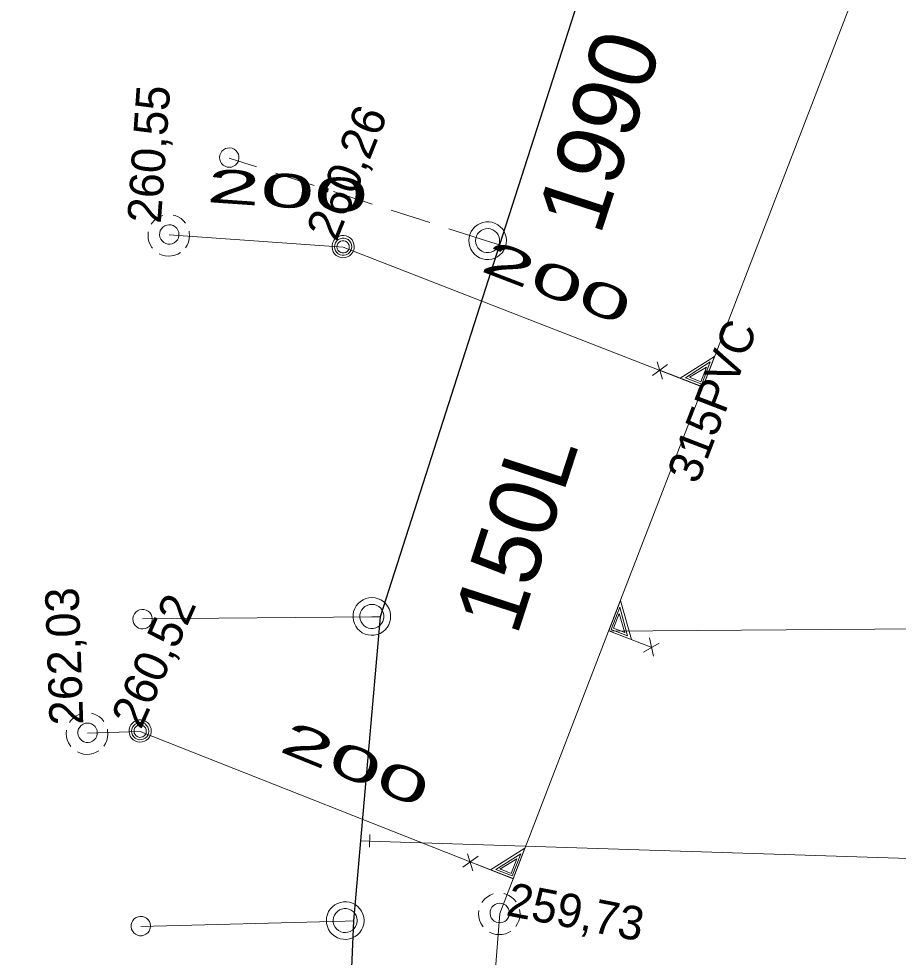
# Model space of a CAD drawing. Extents: x -732096 to -731933, y -1048703 to -1047964.
# Drawn here: x -732046.89 to -732026, y -1048029.6 to -1048007.32 of the extents above; entities that cross this region are included whole.
import ezdxf

# ---------------------------------------------------------------- set-up
doc = ezdxf.new("R2010")
doc.units = 0
doc.header["$LTSCALE"] = 0.32
doc.linetypes.add('MEDIUM_DASHED', pattern=[4.5, 3, -1.5])
doc.layers.add('1', color=7, linetype='Continuous')
for name, color, linetype, lineweight in [('18', 7, 'Continuous', 13), ('20', 7, 'Continuous', 13), ('49', 7, 'Continuous', 13), ('8', 7, 'Continuous', 13)]:
    doc.layers.add(name, color=color, linetype=linetype, lineweight=lineweight)

msp = doc.modelspace()

# ---------------------------------------------------------------- linework, layer by layer
at = {"layer": '18'}
for p, q in [((-732031.842, -1048015.786), (-732031.481, -1048015.527)), ((-732031.733, -1048015.465), (-732031.602, -1048015.874)), ((-732031.814, -1048022.451), (-732031.909, -1048022.017)), ((-732031.682, -1048022.14), (-732032.053, -1048022.355)), ((-732036.237, -1048027.14), (-732036.106, -1048027.549)), ((-732036.346, -1048027.461), (-732035.985, -1048027.202))]:
    msp.add_line(p, q, dxfattribs=at)
for points in [[(-732043.473, -1048011.987), (-732043.544, -1048012.015), (-732043.61, -1048012.054), (-732043.671, -1048012.102), (-732043.722, -1048012.159), (-732043.745, -1048012.193)], [(-732042.931, -1048012.17), (-732042.982, -1048012.112), (-732043.039, -1048012.062), (-732043.105, -1048012.021), (-732043.176, -1048011.992), (-732043.225, -1048011.978)], [(-732043.818, -1048012.379), (-732043.823, -1048012.456), (-732043.818, -1048012.533), (-732043.801, -1048012.608), (-732043.772, -1048012.679), (-732043.732, -1048012.745), (-732043.717, -1048012.767)], [(-732042.936, -1048012.756), (-732042.896, -1048012.691), (-732042.865, -1048012.621), (-732042.845, -1048012.546), (-732042.838, -1048012.47), (-732042.843, -1048012.393), (-732042.848, -1048012.358)], [(-732043.559, -1048012.896), (-732043.49, -1048012.927), (-732043.414, -1048012.946), (-732043.338, -1048012.953), (-732043.262, -1048012.948), (-732043.186, -1048012.931), (-732043.115, -1048012.903), (-732043.054, -1048012.868)], [(-732031.67, -1048015.661), (-732030.648, -1048016.056), (-732030.37, -1048015.337), (-732031.187, -1048015.848)], [(-732031.058, -1048015.843), (-732030.67, -1048015.993), (-732030.467, -1048015.465), (-732031.059, -1048015.842)], [(-732030.963, -1048015.829), (-732030.692, -1048015.934), (-732030.558, -1048015.588), (-732030.964, -1048015.831)], [(-732031.86, -1048022.242), (-732032.881, -1048021.848), (-732032.604, -1048021.13), (-732032.342, -1048022.056)], [(-732032.435, -1048021.967), (-732032.822, -1048021.817), (-732032.618, -1048021.289), (-732032.433, -1048021.968)], [(-732032.495, -1048021.893), (-732032.768, -1048021.788), (-732032.634, -1048021.441), (-732032.496, -1048021.894)], [(-732044.872, -1048024), (-732044.922, -1048023.942), (-732044.98, -1048023.892), (-732045.045, -1048023.851), (-732045.116, -1048023.822), (-732045.165, -1048023.808)], [(-732045.413, -1048023.817), (-732045.484, -1048023.845), (-732045.551, -1048023.884), (-732045.611, -1048023.932), (-732045.662, -1048023.989), (-732045.686, -1048024.023)], [(-732045.758, -1048024.209), (-732045.764, -1048024.286), (-732045.759, -1048024.363), (-732045.742, -1048024.438), (-732045.713, -1048024.509), (-732045.673, -1048024.575), (-732045.657, -1048024.597)], [(-732044.877, -1048024.586), (-732044.836, -1048024.521), (-732044.805, -1048024.451), (-732044.786, -1048024.376), (-732044.778, -1048024.3), (-732044.783, -1048024.223), (-732044.789, -1048024.188)], [(-732045.5, -1048024.726), (-732045.43, -1048024.757), (-732045.355, -1048024.776), (-732045.279, -1048024.783), (-732045.202, -1048024.778), (-732045.127, -1048024.761), (-732045.055, -1048024.733), (-732044.995, -1048024.698)], [(-732036.174, -1048027.336), (-732035.152, -1048027.731), (-732034.874, -1048027.012), (-732035.691, -1048027.523)], [(-732035.562, -1048027.518), (-732035.174, -1048027.668), (-732034.971, -1048027.14), (-732035.563, -1048027.517)], [(-732035.467, -1048027.504), (-732035.196, -1048027.609), (-732035.062, -1048027.263), (-732035.468, -1048027.506)], [(-732035.622, -1048028.097), (-732035.693, -1048028.125), (-732035.76, -1048028.164), (-732035.82, -1048028.212), (-732035.871, -1048028.269), (-732035.895, -1048028.303)], [(-732035.081, -1048028.28), (-732035.131, -1048028.222), (-732035.189, -1048028.172), (-732035.254, -1048028.131), (-732035.325, -1048028.102), (-732035.374, -1048028.088)], [(-732035.086, -1048028.866), (-732035.045, -1048028.801), (-732035.014, -1048028.731), (-732034.995, -1048028.656), (-732034.987, -1048028.58), (-732034.992, -1048028.503), (-732034.998, -1048028.468)], [(-732035.967, -1048028.489), (-732035.973, -1048028.566), (-732035.968, -1048028.643), (-732035.951, -1048028.718), (-732035.922, -1048028.789), (-732035.882, -1048028.855), (-732035.866, -1048028.877)], [(-732035.709, -1048029.006), (-732035.639, -1048029.037), (-732035.564, -1048029.056), (-732035.488, -1048029.063), (-732035.411, -1048029.058), (-732035.336, -1048029.041), (-732035.264, -1048029.013), (-732035.204, -1048028.978)]]:
    msp.add_lwpolyline(points, dxfattribs=at)
for points in [[(-732043.088, -1048012.439), (-732043.095, -1048012.387), (-732043.112, -1048012.337), (-732043.141, -1048012.293), (-732043.179, -1048012.256), (-732043.223, -1048012.229), (-732043.274, -1048012.213), (-732043.326, -1048012.208), (-732043.377, -1048012.215), (-732043.426, -1048012.234), (-732043.47, -1048012.264), (-732043.505, -1048012.303), (-732043.532, -1048012.348), (-732043.546, -1048012.399), (-732043.549, -1048012.451), (-732043.541, -1048012.503), (-732043.521, -1048012.551), (-732043.49, -1048012.594), (-732043.451, -1048012.629), (-732043.404, -1048012.653), (-732043.353, -1048012.667), (-732043.301, -1048012.669), (-732043.25, -1048012.659), (-732043.201, -1048012.637), (-732043.159, -1048012.605), (-732043.127, -1048012.565), (-732043.103, -1048012.518), (-732043.09, -1048012.467)], [(-732038.926, -1048012.727), (-732038.931, -1048012.671), (-732038.948, -1048012.618), (-732038.977, -1048012.569), (-732039.016, -1048012.528), (-732039.061, -1048012.496), (-732039.114, -1048012.474), (-732039.169, -1048012.463), (-732039.225, -1048012.465), (-732039.279, -1048012.478), (-732039.33, -1048012.503), (-732039.375, -1048012.538), (-732039.411, -1048012.581), (-732039.436, -1048012.631), (-732039.451, -1048012.686), (-732039.453, -1048012.742), (-732039.445, -1048012.797), (-732039.424, -1048012.85), (-732039.392, -1048012.896), (-732039.352, -1048012.935), (-732039.304, -1048012.965), (-732039.252, -1048012.984), (-732039.196, -1048012.991), (-732039.139, -1048012.987), (-732039.085, -1048012.97), (-732039.036, -1048012.943), (-732038.995, -1048012.905), (-732038.962, -1048012.86), (-732038.938, -1048012.809), (-732038.926, -1048012.754)], [(-732038.985, -1048012.73), (-732038.99, -1048012.681), (-732039.009, -1048012.635), (-732039.036, -1048012.594), (-732039.073, -1048012.561), (-732039.117, -1048012.539), (-732039.166, -1048012.527), (-732039.215, -1048012.527), (-732039.262, -1048012.539), (-732039.306, -1048012.562), (-732039.343, -1048012.595), (-732039.372, -1048012.636), (-732039.389, -1048012.683), (-732039.394, -1048012.732), (-732039.387, -1048012.781), (-732039.37, -1048012.827), (-732039.342, -1048012.867), (-732039.304, -1048012.9), (-732039.261, -1048012.922), (-732039.212, -1048012.934), (-732039.163, -1048012.933), (-732039.115, -1048012.921), (-732039.071, -1048012.897), (-732039.034, -1048012.864), (-732039.007, -1048012.823), (-732038.99, -1048012.776)], [(-732039.044, -1048012.734), (-732039.049, -1048012.692), (-732039.066, -1048012.654), (-732039.095, -1048012.623), (-732039.129, -1048012.6), (-732039.169, -1048012.589), (-732039.212, -1048012.589), (-732039.252, -1048012.601), (-732039.286, -1048012.624), (-732039.313, -1048012.656), (-732039.33, -1048012.694), (-732039.335, -1048012.735), (-732039.33, -1048012.777), (-732039.311, -1048012.814), (-732039.284, -1048012.846), (-732039.247, -1048012.868), (-732039.208, -1048012.879), (-732039.166, -1048012.878), (-732039.125, -1048012.865), (-732039.092, -1048012.842), (-732039.065, -1048012.809), (-732039.049, -1048012.771)], [(-732043.746, -1048024.227), (-732043.752, -1048024.171), (-732043.769, -1048024.118), (-732043.798, -1048024.069), (-732043.836, -1048024.028), (-732043.882, -1048023.996), (-732043.934, -1048023.974), (-732043.989, -1048023.963), (-732044.045, -1048023.965), (-732044.1, -1048023.978), (-732044.151, -1048024.003), (-732044.195, -1048024.038), (-732044.231, -1048024.081), (-732044.256, -1048024.131), (-732044.271, -1048024.186), (-732044.274, -1048024.242), (-732044.265, -1048024.297), (-732044.244, -1048024.35), (-732044.213, -1048024.396), (-732044.173, -1048024.435), (-732044.125, -1048024.465), (-732044.072, -1048024.484), (-732044.016, -1048024.491), (-732043.96, -1048024.487), (-732043.906, -1048024.47), (-732043.857, -1048024.443), (-732043.815, -1048024.405), (-732043.782, -1048024.36), (-732043.759, -1048024.309), (-732043.747, -1048024.254)], [(-732043.805, -1048024.23), (-732043.811, -1048024.181), (-732043.829, -1048024.135), (-732043.857, -1048024.094), (-732043.894, -1048024.061), (-732043.938, -1048024.039), (-732043.986, -1048024.027), (-732044.035, -1048024.027), (-732044.083, -1048024.039), (-732044.127, -1048024.062), (-732044.164, -1048024.095), (-732044.192, -1048024.136), (-732044.209, -1048024.183), (-732044.215, -1048024.232), (-732044.208, -1048024.281), (-732044.19, -1048024.327), (-732044.162, -1048024.367), (-732044.125, -1048024.4), (-732044.081, -1048024.422), (-732044.032, -1048024.434), (-732043.983, -1048024.433), (-732043.935, -1048024.421), (-732043.892, -1048024.397), (-732043.855, -1048024.364), (-732043.827, -1048024.323), (-732043.811, -1048024.276)], [(-732045.029, -1048024.269), (-732045.035, -1048024.217), (-732045.053, -1048024.167), (-732045.081, -1048024.123), (-732045.119, -1048024.086), (-732045.164, -1048024.059), (-732045.214, -1048024.043), (-732045.266, -1048024.038), (-732045.318, -1048024.045), (-732045.367, -1048024.064), (-732045.411, -1048024.094), (-732045.446, -1048024.133), (-732045.472, -1048024.178), (-732045.487, -1048024.229), (-732045.49, -1048024.281), (-732045.482, -1048024.333), (-732045.461, -1048024.381), (-732045.431, -1048024.424), (-732045.391, -1048024.459), (-732045.345, -1048024.483), (-732045.294, -1048024.497), (-732045.242, -1048024.499), (-732045.19, -1048024.489), (-732045.142, -1048024.467), (-732045.1, -1048024.435), (-732045.067, -1048024.395), (-732045.043, -1048024.348), (-732045.031, -1048024.297)], [(-732043.864, -1048024.234), (-732043.87, -1048024.192), (-732043.887, -1048024.154), (-732043.915, -1048024.123), (-732043.95, -1048024.1), (-732043.99, -1048024.089), (-732044.032, -1048024.089), (-732044.072, -1048024.101), (-732044.107, -1048024.124), (-732044.134, -1048024.156), (-732044.151, -1048024.194), (-732044.156, -1048024.235), (-732044.15, -1048024.277), (-732044.132, -1048024.314), (-732044.104, -1048024.346), (-732044.068, -1048024.368), (-732044.028, -1048024.379), (-732043.986, -1048024.378), (-732043.946, -1048024.365), (-732043.912, -1048024.342), (-732043.885, -1048024.309), (-732043.869, -1048024.271)], [(-732035.238, -1048028.549), (-732035.244, -1048028.497), (-732035.262, -1048028.447), (-732035.29, -1048028.403), (-732035.328, -1048028.366), (-732035.373, -1048028.339), (-732035.423, -1048028.323), (-732035.475, -1048028.318), (-732035.527, -1048028.325), (-732035.576, -1048028.344), (-732035.62, -1048028.374), (-732035.655, -1048028.413), (-732035.681, -1048028.458), (-732035.696, -1048028.509), (-732035.699, -1048028.561), (-732035.691, -1048028.613), (-732035.67, -1048028.661), (-732035.64, -1048028.704), (-732035.6, -1048028.739), (-732035.554, -1048028.763), (-732035.503, -1048028.777), (-732035.451, -1048028.779), (-732035.399, -1048028.769), (-732035.351, -1048028.747), (-732035.309, -1048028.715), (-732035.276, -1048028.675), (-732035.252, -1048028.628), (-732035.24, -1048028.577)]]:
    msp.add_lwpolyline(points, close=True, dxfattribs=at)
at = {"layer": '20'}
for points in [[(-732035.469, -1048028.56), (-732035.152, -1048027.738), (-732032.882, -1048021.854), (-732030.648, -1048016.063), (-732026.359, -1048004.95)], [(-732035.469, -1048028.56), (-732035.152, -1048027.738), (-732032.882, -1048021.854), (-732030.648, -1048016.063), (-732026.359, -1048004.95)], [(-732072.387, -1048040.394), (-732045.426, -1048038.914), (-732043.129, -1048038.788), (-732036.239, -1048038.41), (-732035.469, -1048028.56)], [(-732072.387, -1048040.394), (-732045.426, -1048038.914), (-732043.129, -1048038.788), (-732036.239, -1048038.41), (-732035.469, -1048028.56)]]:
    msp.add_lwpolyline(points, dxfattribs=at)
at = {"layer": '49'}
for p, q in [((-732043.32, -1048012.45), (-732039.19, -1048012.74)), ((-732043.32, -1048012.45), (-732039.19, -1048012.74)), ((-732039.19, -1048012.74), (-732030.648, -1048016.063)), ((-732039.19, -1048012.74), (-732030.648, -1048016.063)), ((-732015.73, -1048021.73), (-732032.882, -1048021.854)), ((-732015.73, -1048021.73), (-732032.882, -1048021.854))]:
    msp.add_line(p, q, dxfattribs=at)
msp.add_lwpolyline([(-732045.26, -1048024.28), (-732044.01, -1048024.24), (-732035.152, -1048027.738)], dxfattribs=at)
msp.add_lwpolyline([(-732045.26, -1048024.28), (-732044.01, -1048024.24), (-732035.152, -1048027.738)], dxfattribs=at)
at = {"layer": '8', "linetype": 'MEDIUM_DASHED'}
for p, q in [((-732035.761, -1048012.597), (-732041.897, -1048010.626)), ((-732035.475, -1048012.689), (-732035.761, -1048012.597))]:
    msp.add_line(p, q, dxfattribs=at)
at = {"layer": '8'}
for p, q in [((-732038.51, -1048021.52), (-732043.954, -1048021.564)), ((-732038.309, -1048021.518), (-732038.51, -1048021.52)), ((-732038.563, -1048026.985), (-732038.553, -1048026.681)), ((-732038.774, -1048026.833), (-732038.559, -1048026.84)), ((-732038.559, -1048026.84), (-732022.559, -1048027.36)), ((-732039.14, -1048028.74), (-732043.997, -1048028.871)), ((-732038.94, -1048028.735), (-732039.14, -1048028.74))]:
    msp.add_line(p, q, dxfattribs=at)
at = {"layer": '8', "lineweight": 25}
msp.add_lwpolyline([(-732033.399, -1047999.11), (-732033.26, -1048005.79), (-732035.475, -1048012.689), (-732038.309, -1048021.518), (-732038.774, -1048026.833), (-732038.94, -1048028.735), (-732039.3, -1048037.077)], dxfattribs=at)
at = {"layer": '8'}
for points in [[(-732041.673, -1048010.685), (-732041.663, -1048010.634), (-732041.665, -1048010.581), (-732041.678, -1048010.53), (-732041.703, -1048010.483), (-732041.738, -1048010.444), (-732041.78, -1048010.413), (-732041.828, -1048010.393), (-732041.88, -1048010.383), (-732041.932, -1048010.387), (-732041.984, -1048010.402), (-732042.029, -1048010.428), (-732042.067, -1048010.463), (-732042.097, -1048010.507), (-732042.116, -1048010.556), (-732042.124, -1048010.608), (-732042.119, -1048010.66), (-732042.104, -1048010.71), (-732042.076, -1048010.755), (-732042.04, -1048010.792), (-732041.995, -1048010.821), (-732041.946, -1048010.839), (-732041.894, -1048010.845), (-732041.842, -1048010.839), (-732041.792, -1048010.821), (-732041.748, -1048010.793), (-732041.711, -1048010.756), (-732041.684, -1048010.711)], [(-732035.332, -1048012.722), (-732035.315, -1048012.651), (-732035.311, -1048012.578), (-732035.318, -1048012.505), (-732035.337, -1048012.435), (-732035.367, -1048012.368), (-732035.407, -1048012.307), (-732035.457, -1048012.254), (-732035.516, -1048012.209), (-732035.58, -1048012.175), (-732035.65, -1048012.151), (-732035.722, -1048012.14), (-732035.796, -1048012.14), (-732035.867, -1048012.152), (-732035.936, -1048012.176), (-732036.001, -1048012.211), (-732036.059, -1048012.255), (-732036.109, -1048012.31), (-732036.149, -1048012.37), (-732036.179, -1048012.437), (-732036.198, -1048012.508), (-732036.204, -1048012.58), (-732036.199, -1048012.653), (-732036.182, -1048012.725), (-732036.154, -1048012.792), (-732036.115, -1048012.854), (-732036.066, -1048012.908), (-732036.01, -1048012.955), (-732035.946, -1048012.991), (-732035.877, -1048013.017), (-732035.805, -1048013.03), (-732035.732, -1048013.032), (-732035.659, -1048013.022), (-732035.589, -1048013), (-732035.524, -1048012.967), (-732035.465, -1048012.923), (-732035.413, -1048012.872), (-732035.372, -1048012.811), (-732035.34, -1048012.746)], [(-732035.485, -1048012.673), (-732035.473, -1048012.616), (-732035.473, -1048012.557), (-732035.484, -1048012.5), (-732035.508, -1048012.446), (-732035.54, -1048012.398), (-732035.583, -1048012.358), (-732035.633, -1048012.327), (-732035.689, -1048012.307), (-732035.746, -1048012.299), (-732035.805, -1048012.303), (-732035.862, -1048012.319), (-732035.913, -1048012.345), (-732035.959, -1048012.382), (-732035.996, -1048012.428), (-732036.023, -1048012.479), (-732036.04, -1048012.536), (-732036.044, -1048012.594), (-732036.036, -1048012.652), (-732036.016, -1048012.707), (-732035.986, -1048012.758), (-732035.946, -1048012.8), (-732035.898, -1048012.834), (-732035.845, -1048012.858), (-732035.788, -1048012.87), (-732035.729, -1048012.871), (-732035.672, -1048012.859), (-732035.618, -1048012.835), (-732035.571, -1048012.802), (-732035.531, -1048012.759), (-732035.5, -1048012.709)], [(-732038.062, -1048021.543), (-732038.062, -1048021.469), (-732038.075, -1048021.397), (-732038.099, -1048021.328), (-732038.134, -1048021.264), (-732038.178, -1048021.206), (-732038.232, -1048021.156), (-732038.293, -1048021.117), (-732038.36, -1048021.086), (-732038.43, -1048021.068), (-732038.504, -1048021.061), (-732038.577, -1048021.066), (-732038.648, -1048021.084), (-732038.715, -1048021.112), (-732038.777, -1048021.151), (-732038.832, -1048021.2), (-732038.877, -1048021.257), (-732038.913, -1048021.321), (-732038.939, -1048021.389), (-732038.952, -1048021.461), (-732038.954, -1048021.535), (-732038.944, -1048021.607), (-732038.922, -1048021.676), (-732038.889, -1048021.742), (-732038.845, -1048021.801), (-732038.793, -1048021.852), (-732038.733, -1048021.894), (-732038.668, -1048021.926), (-732038.597, -1048021.946), (-732038.524, -1048021.955), (-732038.451, -1048021.952), (-732038.379, -1048021.936), (-732038.311, -1048021.909), (-732038.248, -1048021.872), (-732038.192, -1048021.825), (-732038.145, -1048021.769), (-732038.107, -1048021.707), (-732038.081, -1048021.639), (-732038.065, -1048021.568)], [(-732044.183, -1048021.575), (-732044.177, -1048021.627), (-732044.158, -1048021.677), (-732044.13, -1048021.721), (-732044.092, -1048021.757), (-732044.047, -1048021.784), (-732043.996, -1048021.799), (-732043.944, -1048021.804), (-732043.892, -1048021.796), (-732043.844, -1048021.777), (-732043.8, -1048021.747), (-732043.765, -1048021.707), (-732043.74, -1048021.662), (-732043.725, -1048021.611), (-732043.723, -1048021.559), (-732043.731, -1048021.507), (-732043.752, -1048021.459), (-732043.783, -1048021.416), (-732043.823, -1048021.382), (-732043.869, -1048021.358), (-732043.92, -1048021.345), (-732043.972, -1048021.343), (-732044.024, -1048021.354), (-732044.072, -1048021.376), (-732044.114, -1048021.408), (-732044.147, -1048021.449), (-732044.17, -1048021.496), (-732044.182, -1048021.547)], [(-732038.223, -1048021.53), (-732038.224, -1048021.472), (-732038.238, -1048021.415), (-732038.262, -1048021.362), (-732038.297, -1048021.315), (-732038.34, -1048021.275), (-732038.391, -1048021.246), (-732038.447, -1048021.228), (-732038.505, -1048021.221), (-732038.563, -1048021.227), (-732038.62, -1048021.245), (-732038.671, -1048021.273), (-732038.715, -1048021.31), (-732038.751, -1048021.357), (-732038.777, -1048021.41), (-732038.791, -1048021.466), (-732038.794, -1048021.525), (-732038.784, -1048021.583), (-732038.763, -1048021.638), (-732038.731, -1048021.686), (-732038.69, -1048021.729), (-732038.642, -1048021.76), (-732038.587, -1048021.783), (-732038.53, -1048021.793), (-732038.472, -1048021.792), (-732038.414, -1048021.779), (-732038.361, -1048021.754), (-732038.314, -1048021.719), (-732038.276, -1048021.675), (-732038.247, -1048021.625), (-732038.229, -1048021.569)], [(-732038.693, -1048028.717), (-732038.701, -1048028.644), (-732038.72, -1048028.573), (-732038.751, -1048028.507), (-732038.793, -1048028.447), (-732038.843, -1048028.393), (-732038.901, -1048028.35), (-732038.966, -1048028.317), (-732039.036, -1048028.293), (-732039.108, -1048028.282), (-732039.182, -1048028.283), (-732039.254, -1048028.296), (-732039.323, -1048028.32), (-732039.386, -1048028.355), (-732039.444, -1048028.401), (-732039.494, -1048028.455), (-732039.533, -1048028.516), (-732039.563, -1048028.584), (-732039.581, -1048028.654), (-732039.587, -1048028.727), (-732039.581, -1048028.8), (-732039.563, -1048028.871), (-732039.535, -1048028.938), (-732039.495, -1048029), (-732039.446, -1048029.054), (-732039.389, -1048029.099), (-732039.325, -1048029.135), (-732039.256, -1048029.16), (-732039.184, -1048029.173), (-732039.111, -1048029.174), (-732039.038, -1048029.164), (-732038.968, -1048029.141), (-732038.903, -1048029.107), (-732038.844, -1048029.064), (-732038.794, -1048029.011), (-732038.752, -1048028.95), (-732038.721, -1048028.885), (-732038.701, -1048028.814), (-732038.693, -1048028.742)], [(-732038.854, -1048028.721), (-732038.861, -1048028.663), (-732038.881, -1048028.607), (-732038.91, -1048028.557), (-732038.95, -1048028.514), (-732038.997, -1048028.479), (-732039.051, -1048028.456), (-732039.108, -1048028.443), (-732039.167, -1048028.443), (-732039.224, -1048028.454), (-732039.278, -1048028.477), (-732039.326, -1048028.511), (-732039.366, -1048028.553), (-732039.397, -1048028.602), (-732039.418, -1048028.658), (-732039.426, -1048028.715), (-732039.423, -1048028.774), (-732039.407, -1048028.831), (-732039.381, -1048028.883), (-732039.344, -1048028.928), (-732039.299, -1048028.966), (-732039.247, -1048028.993), (-732039.191, -1048029.009), (-732039.133, -1048029.014), (-732039.075, -1048029.006), (-732039.019, -1048028.988), (-732038.969, -1048028.958), (-732038.926, -1048028.918), (-732038.892, -1048028.871), (-732038.868, -1048028.817), (-732038.856, -1048028.76)], [(-732043.765, -1048028.853), (-732043.772, -1048028.801), (-732043.792, -1048028.751), (-732043.821, -1048028.708), (-732043.86, -1048028.672), (-732043.905, -1048028.646), (-732043.956, -1048028.632), (-732044.008, -1048028.628), (-732044.06, -1048028.637), (-732044.108, -1048028.657), (-732044.151, -1048028.688), (-732044.185, -1048028.728), (-732044.21, -1048028.774), (-732044.224, -1048028.825), (-732044.225, -1048028.877), (-732044.216, -1048028.929), (-732044.194, -1048028.976), (-732044.163, -1048029.019), (-732044.122, -1048029.052), (-732044.075, -1048029.075), (-732044.024, -1048029.088), (-732043.972, -1048029.088), (-732043.92, -1048029.077), (-732043.872, -1048029.054), (-732043.831, -1048029.021), (-732043.799, -1048028.98), (-732043.777, -1048028.932), (-732043.766, -1048028.881)]]:
    msp.add_lwpolyline(points, close=True, dxfattribs=at)

# ---------------------------------------------------------------- texts
at = {"layer": '1'}
for s, height, rotation, p in [('1990', 1.6, 72, (-732033.086, -1048012.491)), ('260,55', 0.8, 86, (-732043.52, -1048012.192)), ('260,26', 0.8, 68, (-732039.348, -1048012.63)), ('315PVC', 0.8, 69, (-732030.768, -1048018.393)), ('150L', 1.6, 72, (-732035.063, -1048021.996)), ('262,03', 0.8, 92, (-732045.36, -1048024.076)), ('260,52', 0.8, 66, (-732043.993, -1048024.212)), ('259,73', 0.8, 349, (-732035.344, -1048028.6))]:
    msp.add_text(s, height=height, rotation=rotation, dxfattribs=at).set_placement(p)
for rotation, width, p in [(356, 2.15, (-732042.455, -1048011.667)), (339, 2.05, (-732035.96, -1048013.294)), (338, 2.05, (-732040.743, -1048024.698))]:
    msp.add_text('200 ', height=0.8, rotation=rotation, dxfattribs=dict(at, width=width)).set_placement(p)

doc.saveas('drawing.dxf')
